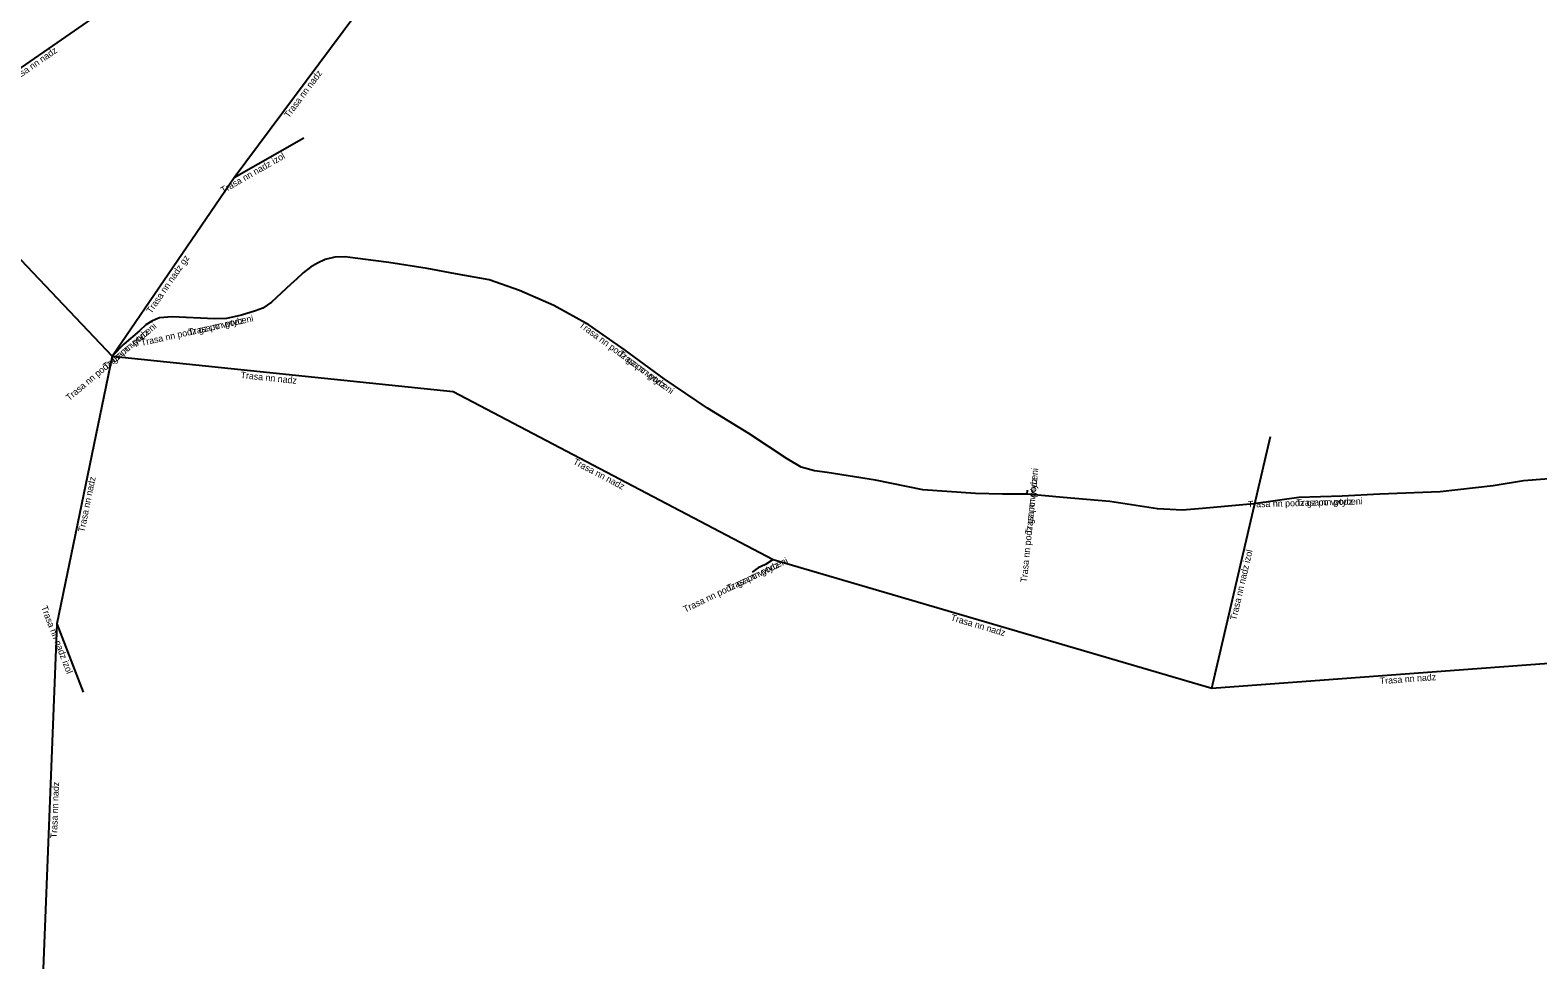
# Model space of a CAD drawing. Extents: x -772942 to -772530, y -1033745 to -1033298.
# Drawn here: x -772879.6 to -772765.4, y -1033629.2 to -1033558.1 of the extents above; entities that cross this region are included whole.
import ezdxf

# ---------------------------------------------------------------- set-up
doc = ezdxf.new("R2010")
doc.units = 0
doc.layers.add('Popiskový text - Ostatní atributy Trasy', color=7, linetype='Continuous')
doc.layers.add('Spojnice NN', color=7, linetype='Continuous')

msp = doc.modelspace()

# ---------------------------------------------------------------- linework, layer by layer
at = {"layer": 'Spojnice NN'}
for points in [[(-772868.87, -1033553.01), (-772888.63, -1033566.69)], [(-772864.11, -1033569.24), (-772853.14, -1033554.49)], [(-772864.11, -1033569.24), (-772858.84, -1033566.23)], [(-772888.63, -1033566.69), (-772873.36, -1033582.78)], [(-772873.36, -1033582.78), (-772864.11, -1033569.24)], [(-772804.09, -1033593.21), (-772805.95, -1033593.21), (-772808, -1033593.16), (-772811.99, -1033592.89), (-772815.57, -1033592.16), (-772819.22, -1033591.57), (-772820.2, -1033591.45), (-772821.19, -1033591.18), (-772822.26, -1033590.53), (-772825.17, -1033588.63), (-772828.28, -1033586.71), (-772831.56, -1033584.49), (-772834.59, -1033582.26), (-772837.27, -1033580.41), (-772839.91, -1033578.93), (-772842.51, -1033577.8), (-772844.82, -1033577), (-772847.36, -1033576.53), (-772849.5, -1033576.13), (-772852.41, -1033575.69), (-772854.95, -1033575.35), (-772855.72, -1033575.25), (-772856.51, -1033575.28), (-772857.23, -1033575.44), (-772857.8, -1033575.72), (-772858.34, -1033576.04), (-772858.89, -1033576.46), (-772859.4, -1033576.94), (-772859.83, -1033577.33)], [(-772804.09, -1033593.21), (-772805.95, -1033593.21), (-772808, -1033593.16), (-772811.99, -1033592.89), (-772815.57, -1033592.16), (-772819.22, -1033591.57), (-772820.2, -1033591.45), (-772821.19, -1033591.18), (-772822.26, -1033590.53), (-772825.17, -1033588.63), (-772828.28, -1033586.71), (-772831.56, -1033584.49), (-772834.59, -1033582.26), (-772837.27, -1033580.41), (-772839.91, -1033578.93), (-772842.51, -1033577.8), (-772844.82, -1033577), (-772847.36, -1033576.53), (-772849.5, -1033576.13), (-772852.41, -1033575.69), (-772854.95, -1033575.35), (-772855.72, -1033575.25), (-772856.51, -1033575.28), (-772857.23, -1033575.44), (-772857.8, -1033575.72), (-772858.34, -1033576.04), (-772858.89, -1033576.46), (-772859.4, -1033576.94), (-772859.83, -1033577.33)], [(-772859.83, -1033577.33), (-772861.3, -1033578.67), (-772861.96, -1033579.13), (-772862.51, -1033579.34), (-772863.56, -1033579.66), (-772864.69, -1033579.91), (-772865.61, -1033579.94), (-772868.8, -1033579.79), (-772869.78, -1033579.86), (-772870.07, -1033579.99)], [(-772859.83, -1033577.33), (-772861.3, -1033578.67), (-772861.96, -1033579.13), (-772862.51, -1033579.34), (-772863.56, -1033579.66), (-772864.69, -1033579.91), (-772865.61, -1033579.94), (-772868.8, -1033579.79), (-772869.78, -1033579.86), (-772870.07, -1033579.99)], [(-772870.07, -1033579.99), (-772870.34, -1033580.11), (-772870.81, -1033580.4), (-772871.28, -1033580.85), (-772872.48, -1033581.86), (-772873.36, -1033582.78)], [(-772870.07, -1033579.99), (-772870.34, -1033580.11), (-772870.81, -1033580.4), (-772871.28, -1033580.85), (-772872.48, -1033581.86), (-772873.36, -1033582.78)], [(-772873.36, -1033582.78), (-772877.55, -1033603.04)], [(-772873.36, -1033582.78), (-772847.54, -1033585.44)], [(-772847.54, -1033585.44), (-772823.31, -1033598.16)], [(-772790.12, -1033607.9), (-772785.67, -1033588.85)], [(-772757.02, -1033591.53), (-772759.52, -1033591.58), (-772762.34, -1033591.87), (-772766.52, -1033592.22), (-772768.82, -1033592.59), (-772772.83, -1033593.04), (-772777.4, -1033593.21), (-772780.24, -1033593.38), (-772783.53, -1033593.47), (-772786.92, -1033593.96), (-772790.83, -1033594.3), (-772792.34, -1033594.42), (-772794.22, -1033594.33), (-772797.84, -1033593.77), (-772801.37, -1033593.47), (-772804.09, -1033593.21)], [(-772757.02, -1033591.53), (-772759.52, -1033591.58), (-772762.34, -1033591.87), (-772766.52, -1033592.22), (-772768.82, -1033592.59), (-772772.83, -1033593.04), (-772777.4, -1033593.21), (-772780.24, -1033593.38), (-772783.53, -1033593.47), (-772786.92, -1033593.96), (-772790.83, -1033594.3), (-772792.34, -1033594.42), (-772794.22, -1033594.33), (-772797.84, -1033593.77), (-772801.37, -1033593.47), (-772804.09, -1033593.21)], [(-772804.09, -1033593.21), (-772804.06, -1033592.91)], [(-772804.09, -1033593.21), (-772804.06, -1033592.91)], [(-772823.31, -1033598.16), (-772823.89, -1033598.53), (-772824.45, -1033598.8), (-772824.91, -1033599.11)], [(-772823.31, -1033598.16), (-772823.89, -1033598.53), (-772824.45, -1033598.8), (-772824.91, -1033599.11)], [(-772823.31, -1033598.16), (-772790.12, -1033607.9)], [(-772877.55, -1033603.04), (-772878.57, -1033629.15)], [(-772877.55, -1033603.04), (-772875.55, -1033608.21)], [(-772790.12, -1033607.9), (-772758.47, -1033605.55)]]:
    msp.add_lwpolyline(points, dxfattribs=at)

# ---------------------------------------------------------------- texts
at = {"layer": 'Popiskový text - Ostatní atributy Trasy'}
for s, rotation, p in [('Trasa nn nadz', 34.7016, (-772880.97, -1033562.17)), ('Trasa nn nadz', 53.359, (-772859.98, -1033564.78)), ('Trasa nn nadz izol', 29.7288, (-772864.96, -1033570.47)), ('Trasa nn nadz gz', 55.6606, (-772870.39, -1033579.59)), ('Trasa nn podz gz po vytyceni', 12.4751, (-772871.12, -1033582)), ('Trasa nn podz', 12.4751, (-772867.52, -1033581.2)), ('Trasa nn podz gz po vytyceni', 40.0862, (-772876.6, -1033586.18)), ('Trasa nn podz', 40.0862, (-772873.78, -1033583.81)), ('Trasa nn podz gz po vytyceni', 323.6479, (-772838.06, -1033580.51)), ('Trasa nn podz', 323.6479, (-772835.09, -1033582.7)), ('Trasa nn nadz', 354.1286, (-772863.65, -1033584.43)), ('Trasa nn nadz', 332.2946, (-772838.51, -1033590.91)), ('Trasa nn podz gz po vytyceni', 84.2894, (-772804.11, -1033599.92)), ('Trasa nn nadz', 78.3067, (-772875.46, -1033596.13)), ('Trasa nn podz', 84.2894, (-772803.74, -1033596.26)), ('Trasa nn podz gz po vytyceni', 1.567, (-772787.38, -1033594.23)), ('Trasa nn podz', 1.567, (-772783.7, -1033594.12)), ('Trasa nn podz gz po vytyceni', 25.7407, (-772829.98, -1033602.19)), ('Trasa nn nadz izol', 76.8509, (-772788.26, -1033602.8)), ('Trasa nn podz', 25.7407, (-772826.66, -1033600.59)), ('Trasa nn nadz izol', 291.1798, (-772878.75, -1033601.77)), ('Trasa nn nadz', 343.6387, (-772809.92, -1033602.77)), ('Trasa nn nadz', 4.246, (-772777.38, -1033607.61)), ('Trasa nn nadz', 87.7714, (-772877.53, -1033619.27))]:
    msp.add_text(s, height=0.5, rotation=rotation, dxfattribs=at).set_placement(p)

doc.saveas('drawing.dxf')
